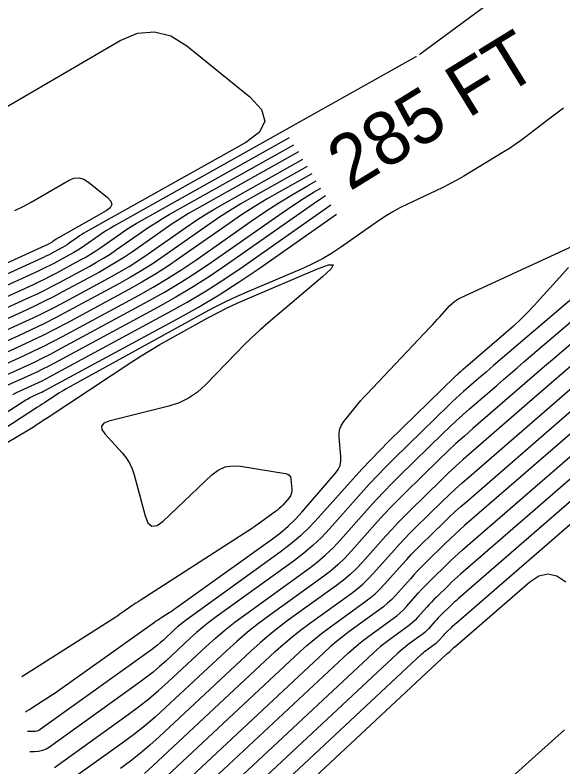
# Model space of a CAD drawing. Extents: x 1768942 to 1774819, y 723037 to 732099.
# Drawn here: x 1770484.7 to 1770546.4, y 726452.6 to 726537.2 of the extents above; entities that cross this region are included whole.
import ezdxf

# ---------------------------------------------------------------- set-up
doc = ezdxf.new("R2010")
doc.units = 0
doc.layers.add('R_Contour Annot', color=7, linetype='Continuous')
doc.layers.add('R_Contours', color=7, linetype='Continuous')

msp = doc.modelspace()

# ---------------------------------------------------------------- linework, layer by layer
at = {"layer": 'R_Contours'}
for points in [[(1770569.11, 726561.412), (1770530.313, 726532.796), (1770530.288, 726532.777), (1770530.263, 726532.757), (1770530.241, 726532.741)], [(1770478.44, 726523.752), (1770496.565, 726534.321), (1770498.514, 726535.148), (1770500.412, 726535.328), (1770502.261, 726534.86), (1770504.06, 726533.745), (1770511.158, 726527.991), (1770512.461, 726526.593), (1770512.823, 726525.275), (1770512.243, 726524.037), (1770510.721, 726522.88), (1770492.736, 726512.797), (1770492.488, 726512.653), (1770492.244, 726512.504), (1770492.003, 726512.348), (1770491.766, 726512.187), (1770490.827, 726511.529), (1770490.59, 726511.368), (1770490.348, 726511.214), (1770490.102, 726511.067), (1770489.852, 726510.927), (1770488.762, 726510.338), (1770488.495, 726510.197), (1770488.225, 726510.06), (1770487.954, 726509.928), (1770487.68, 726509.801), (1770464.867, 726499.407)], [(1770529.896, 726532.528), (1770529.881, 726532.522), (1770529.856, 726532.51), (1770529.831, 726532.497), (1770529.806, 726532.484), (1770495.854, 726513.448), (1770495.432, 726513.205), (1770495.016, 726512.951), (1770494.607, 726512.686), (1770494.205, 726512.412), (1770492.607, 726511.292), (1770492.204, 726511.019), (1770491.793, 726510.757), (1770491.375, 726510.507), (1770490.95, 726510.269), (1770489.095, 726509.268), (1770488.641, 726509.027), (1770488.183, 726508.795), (1770487.721, 726508.57), (1770487.256, 726508.353), (1770466.953, 726499.103)], [(1770546.443, 726526.741), (1770545.83, 726526.292), (1770545.222, 726525.837), (1770544.618, 726525.375), (1770542.213, 726523.517), (1770541.606, 726523.061), (1770540.986, 726522.624), (1770540.354, 726522.205), (1770539.709, 726521.804), (1770535.203, 726519.089), (1770534.433, 726518.639), (1770533.651, 726518.21), (1770532.859, 726517.801), (1770532.056, 726517.413), (1770528.821, 726515.901), (1770528.021, 726515.507), (1770527.241, 726515.079), (1770526.481, 726514.617), (1770525.74, 726514.123), (1770521.337, 726511.045), (1770520.344, 726510.389), (1770519.321, 726509.787), (1770518.269, 726509.24), (1770517.185, 726508.747), (1770511.082, 726506.158), (1770509.707, 726505.554), (1770508.35, 726504.915), (1770507.009, 726504.241), (1770505.685, 726503.533), (1770490.481, 726495.139), (1770490.204, 726494.982), (1770489.93, 726494.82), (1770489.659, 726494.652), (1770489.392, 726494.479), (1770488.329, 726493.777), (1770488.063, 726493.601), (1770487.797, 726493.427), (1770487.53, 726493.252), (1770487.263, 726493.079), (1770478.809, 726487.603)], [(1770469.039, 726498.799), (1770486.831, 726506.906), (1770487.489, 726507.212), (1770488.141, 726507.529), (1770488.787, 726507.858), (1770489.428, 726508.197), (1770492.047, 726509.611), (1770492.648, 726509.947), (1770493.238, 726510.3), (1770493.818, 726510.669), (1770494.387, 726511.056), (1770496.643, 726512.636), (1770497.212, 726513.024), (1770497.789, 726513.397), (1770498.376, 726513.756), (1770498.972, 726514.1), (1770515.606, 726523.426)], [(1770471.124, 726498.496), (1770486.407, 726505.458), (1770487.256, 726505.854), (1770488.098, 726506.264), (1770488.934, 726506.688), (1770489.762, 726507.126), (1770493.144, 726508.953), (1770493.92, 726509.387), (1770494.683, 726509.843), (1770495.432, 726510.32), (1770496.167, 726510.82), (1770499.081, 726512.861), (1770499.816, 726513.362), (1770500.562, 726513.844), (1770501.32, 726514.307), (1770502.09, 726514.752), (1770516.108, 726522.611)], [(1770516.61, 726521.796), (1770505.209, 726515.404), (1770504.265, 726514.859), (1770503.335, 726514.291), (1770502.42, 726513.7), (1770501.52, 726513.086), (1770497.947, 726510.583), (1770497.046, 726509.971), (1770496.128, 726509.386), (1770495.193, 726508.827), (1770494.242, 726508.295), (1770490.095, 726506.056), (1770489.08, 726505.518), (1770488.056, 726504.999), (1770487.023, 726504.496), (1770485.982, 726504.011), (1770473.21, 726498.192)], [(1770475.296, 726497.888), (1770485.558, 726502.564), (1770486.791, 726503.138), (1770488.014, 726503.733), (1770489.226, 726504.349), (1770490.429, 726504.985), (1770495.339, 726507.637), (1770496.466, 726508.267), (1770497.572, 726508.928), (1770498.66, 726509.622), (1770499.727, 726510.347), (1770503.958, 726513.31), (1770505.025, 726514.038), (1770506.108, 726514.737), (1770507.209, 726515.41), (1770508.327, 726516.055), (1770517.112, 726520.981)], [(1770517.614, 726520.166), (1770511.445, 726516.707), (1770510.153, 726515.961), (1770508.881, 726515.184), (1770507.629, 726514.375), (1770506.397, 726513.535), (1770501.507, 726510.11), (1770500.274, 726509.272), (1770499.017, 726508.471), (1770497.738, 726507.707), (1770496.437, 726506.979), (1770490.762, 726503.914), (1770489.372, 726503.179), (1770487.971, 726502.468), (1770486.558, 726501.78), (1770485.133, 726501.116), (1770477.382, 726497.584)], [(1770518.116, 726519.351), (1770514.563, 726517.359), (1770513.097, 726516.513), (1770511.654, 726515.631), (1770510.233, 726514.713), (1770508.835, 726513.76), (1770503.287, 726509.874), (1770501.888, 726508.923), (1770500.462, 726508.014), (1770499.011, 726507.147), (1770497.534, 726506.321), (1770490.564, 726502.557), (1770489.254, 726501.864), (1770487.933, 726501.193), (1770486.601, 726500.545), (1770485.258, 726499.919), (1770479.467, 726497.281)], [(1770484.725, 726515.23), (1770485.661, 726515.653), (1770486.571, 726516.143), (1770490.764, 726518.588), (1770491.348, 726518.836), (1770491.916, 726518.89), (1770492.469, 726518.75), (1770493.008, 726518.416), (1770495.133, 726516.693), (1770495.523, 726516.275), (1770495.631, 726515.88), (1770495.457, 726515.51), (1770495.002, 726515.163), (1770489.618, 726512.145), (1770489.544, 726512.102), (1770489.471, 726512.057), (1770489.399, 726512.011), (1770489.328, 726511.962), (1770489.046, 726511.765), (1770488.976, 726511.717), (1770488.903, 726511.671), (1770488.83, 726511.627), (1770488.755, 726511.585), (1770488.428, 726511.409), (1770488.348, 726511.367), (1770488.268, 726511.326), (1770488.187, 726511.286), (1770488.105, 726511.248), (1770462.781, 726499.71)], [(1770481.223, 726496.826), (1770485.685, 726498.86), (1770486.796, 726499.377), (1770487.898, 726499.913), (1770488.991, 726500.468), (1770490.074, 726501.042), (1770498.631, 726505.663), (1770500.284, 726506.587), (1770501.907, 726507.557), (1770503.502, 726508.574), (1770505.068, 726509.637), (1770511.296, 726514), (1770512.849, 726515.059), (1770514.426, 726516.078), (1770516.029, 726517.057), (1770517.656, 726517.997), (1770518.618, 726518.536)], [(1770482.584, 726496.193), (1770486.113, 726497.8), (1770486.991, 726498.21), (1770487.863, 726498.634), (1770488.727, 726499.073), (1770489.584, 726499.526), (1770499.729, 726505.005), (1770501.556, 726506.027), (1770503.352, 726507.1), (1770505.116, 726508.225), (1770506.848, 726509.401), (1770514.793, 726514.966), (1770515.978, 726515.774), (1770517.182, 726516.552), (1770518.405, 726517.3), (1770519.124, 726517.715)], [(1770519.659, 726516.846), (1770519.107, 726516.49), (1770518.289, 726515.932), (1770508.628, 726509.164), (1770506.73, 726507.875), (1770504.797, 726506.643), (1770502.829, 726505.467), (1770500.826, 726504.348), (1770489.093, 726498.01), (1770488.463, 726497.677), (1770487.827, 726497.354), (1770487.187, 726497.042), (1770486.54, 726496.741), (1770483.944, 726495.559)], [(1770484.49, 726494.517), (1770484.894, 726494.728), (1770485.305, 726494.925), (1770486.968, 726495.682), (1770487.382, 726495.875), (1770487.792, 726496.075), (1770488.199, 726496.281), (1770488.603, 726496.495), (1770501.924, 726503.69), (1770504.102, 726504.907), (1770506.242, 726506.186), (1770508.344, 726507.526), (1770510.408, 726508.928), (1770520.278, 726515.842)], [(1770476.003, 726487.512), (1770485.965, 726493.908), (1770486.135, 726494.013), (1770486.309, 726494.112), (1770486.486, 726494.205), (1770486.666, 726494.291), (1770487.395, 726494.623), (1770487.577, 726494.707), (1770487.757, 726494.795), (1770487.935, 726494.886), (1770488.112, 726494.979), (1770503.021, 726503.032), (1770505.374, 726504.347), (1770507.687, 726505.729), (1770509.958, 726507.177), (1770512.188, 726508.691), (1770520.916, 726514.805)], [(1770485.923, 726458.831), (1770486.034, 726458.899), (1770486.295, 726459.063), (1770488.027, 726460.163), (1770488.401, 726460.404), (1770488.772, 726460.65), (1770489.14, 726460.9), (1770489.504, 726461.155), (1770500.427, 726468.905), (1770500.63, 726469.047), (1770500.834, 726469.186), (1770501.04, 726469.323), (1770501.247, 726469.458), (1770502.081, 726469.993), (1770502.288, 726470.128), (1770502.494, 726470.265), (1770502.698, 726470.405), (1770502.9, 726470.548), (1770513.714, 726478.288), (1770514.615, 726478.974), (1770515.47, 726479.709), (1770516.28, 726480.494), (1770517.044, 726481.328), (1770520.803, 726485.681), (1770521.1, 726486.098), (1770521.298, 726486.546), (1770521.398, 726487.027), (1770521.399, 726487.538), (1770521.202, 726489.704), (1770521.201, 726490.191), (1770521.29, 726490.65), (1770521.469, 726491.083), (1770521.737, 726491.489), (1770522.989, 726493.058), (1770523.306, 726493.447), (1770523.631, 726493.829), (1770523.964, 726494.204), (1770524.305, 726494.572), (1770531.399, 726502.066), (1770531.68, 726502.365), (1770531.959, 726502.665), (1770532.237, 726502.967), (1770532.514, 726503.27), (1770533.616, 726504.485), (1770533.904, 726504.772), (1770534.216, 726505.027), (1770534.552, 726505.248), (1770534.912, 726505.436), (1770550.369, 726512.559)], [(1770474.411, 726483.519), (1770486.249, 726490.55), (1770486.438, 726490.664), (1770486.626, 726490.779), (1770486.813, 726490.896), (1770486.998, 726491.015), (1770487.739, 726491.495), (1770487.924, 726491.615), (1770488.108, 726491.736), (1770488.293, 726491.857), (1770488.477, 726491.978), (1770497.882, 726498.196), (1770498.918, 726498.866), (1770499.967, 726499.515), (1770501.028, 726500.143), (1770502.103, 726500.75), (1770506.425, 726503.137), (1770507.513, 726503.719), (1770508.615, 726504.273), (1770509.73, 726504.798), (1770510.86, 726505.294), (1770518.766, 726508.648), (1770520.007, 726509.104), (1770520.513, 726509.106), (1770520.283, 726508.656), (1770519.318, 726507.752), (1770513.214, 726502.577), (1770512.279, 726501.763), (1770511.364, 726500.925), (1770510.472, 726500.065), (1770509.601, 726499.182), (1770506.162, 726495.603), (1770505.259, 726494.782), (1770504.27, 726494.109), (1770503.196, 726493.584), (1770502.035, 726493.206), (1770495.287, 726491.505), (1770494.735, 726491.283), (1770494.48, 726490.973), (1770494.521, 726490.573), (1770494.86, 726490.084), (1770496.807, 726487.949), (1770497.256, 726487.395), (1770497.63, 726486.799), (1770497.928, 726486.163), (1770498.15, 726485.485), (1770499.371, 726480.866), (1770499.697, 726480.078), (1770500.145, 726479.719), (1770500.715, 726479.788), (1770501.407, 726480.287), (1770506.881, 726485.468), (1770507.599, 726486.018), (1770508.378, 726486.367), (1770509.218, 726486.515), (1770510.12, 726486.463), (1770515.164, 726485.64), (1770515.409, 726485.566), (1770515.591, 726485.433), (1770515.711, 726485.242), (1770515.768, 726484.992), (1770515.871, 726483.861), (1770515.87, 726483.598), (1770515.819, 726483.35), (1770515.716, 726483.119), (1770515.563, 726482.904), (1770514.849, 726482.076), (1770514.665, 726481.876), (1770514.47, 726481.687), (1770514.264, 726481.51), (1770514.047, 726481.345), (1770512.134, 726479.975), (1770511.739, 726479.696), (1770511.341, 726479.423), (1770510.939, 726479.154), (1770510.534, 726478.89), (1770498.81, 726471.369), (1770498.578, 726471.218), (1770498.348, 726471.065), (1770498.12, 726470.909), (1770497.893, 726470.75), (1770496.991, 726470.11), (1770496.765, 726469.952), (1770496.537, 726469.796), (1770496.306, 726469.644), (1770496.074, 726469.494), (1770485.492, 726462.773)], [(1770547.007, 726508.804), (1770543.129, 726504.529), (1770542.382, 726503.73), (1770541.61, 726502.956), (1770540.814, 726502.207), (1770539.994, 726501.483), (1770535.158, 726497.345), (1770535.08, 726497.278), (1770535.002, 726497.211), (1770534.924, 726497.144), (1770534.846, 726497.077), (1770534.536, 726496.808), (1770534.459, 726496.74), (1770534.383, 726496.671), (1770534.308, 726496.601), (1770534.234, 726496.529), (1770526.801, 726489.266), (1770525.766, 726488.236), (1770524.749, 726487.189), (1770523.75, 726486.125), (1770522.77, 726485.043), (1770518.885, 726480.68), (1770517.887, 726479.619), (1770516.835, 726478.617), (1770515.731, 726477.674), (1770514.573, 726476.79), (1770504.033, 726469.188), (1770503.686, 726468.929), (1770503.347, 726468.659), (1770503.016, 726468.379), (1770502.695, 726468.088), (1770501.426, 726466.903), (1770501.105, 726466.612), (1770500.774, 726466.332), (1770500.435, 726466.063), (1770500.086, 726465.805), (1770487.584, 726456.847), (1770487.413, 726456.743), (1770487.232, 726456.669), (1770487.041, 726456.625), (1770486.841, 726456.612), (1770486.165, 726456.617)], [(1770550.656, 726508.106), (1770538.573, 726497.767), (1770538.15, 726497.405), (1770537.727, 726497.041), (1770537.305, 726496.677), (1770536.884, 726496.312), (1770535.199, 726494.852), (1770534.781, 726494.484), (1770534.368, 726494.11), (1770533.961, 726493.73), (1770533.56, 726493.343), (1770527.394, 726487.317), (1770526.443, 726486.371), (1770525.508, 726485.409), (1770524.591, 726484.431), (1770523.69, 726483.437), (1770520.121, 726479.43), (1770519.204, 726478.455), (1770518.238, 726477.534), (1770517.223, 726476.668), (1770516.16, 726475.856), (1770507.359, 726469.508), (1770506.604, 726468.945), (1770505.868, 726468.359), (1770505.15, 726467.75), (1770504.452, 726467.118), (1770501.696, 726464.544), (1770500.997, 726463.912), (1770500.279, 726463.304), (1770499.542, 726462.72), (1770498.785, 726462.159), (1770488.615, 726454.872), (1770488.231, 726454.639), (1770487.826, 726454.473), (1770487.399, 726454.375), (1770486.951, 726454.345), (1770486.413, 726454.349)], [(1770489.168, 726452.554), (1770497.484, 726458.513), (1770498.649, 726459.377), (1770499.784, 726460.277), (1770500.89, 726461.213), (1770501.966, 726462.185), (1770506.209, 726466.148), (1770507.284, 726467.121), (1770508.389, 726468.059), (1770509.522, 726468.961), (1770510.685, 726469.828), (1770517.746, 726474.921), (1770518.716, 726475.662), (1770519.641, 726476.451), (1770520.521, 726477.29), (1770521.357, 726478.179), (1770524.61, 726481.832), (1770525.431, 726482.738), (1770526.267, 726483.629), (1770527.119, 726484.506), (1770527.986, 726485.368), (1770532.886, 726490.157), (1770533.614, 726490.858), (1770534.353, 726491.549), (1770535.103, 726492.228), (1770535.862, 726492.897), (1770538.921, 726495.548), (1770539.686, 726496.21), (1770540.453, 726496.871), (1770541.22, 726497.531), (1770541.988, 726498.19), (1770552.137, 726506.873)], [(1770553.617, 726505.64), (1770545.404, 726498.612), (1770544.29, 726497.657), (1770543.178, 726496.701), (1770542.068, 726495.743), (1770540.959, 726494.784), (1770536.24, 726490.694), (1770535.281, 726489.85), (1770534.335, 726488.992), (1770533.402, 726488.12), (1770532.482, 726487.234), (1770528.578, 726483.419), (1770527.796, 726482.641), (1770527.027, 726481.849), (1770526.272, 726481.045), (1770525.53, 726480.227), (1770522.593, 726476.928), (1770521.838, 726476.126), (1770521.043, 726475.368), (1770520.208, 726474.655), (1770519.333, 726473.987), (1770513.404, 726469.711), (1770512.134, 726468.763), (1770510.895, 726467.777), (1770509.688, 726466.753), (1770508.512, 726465.689), (1770501.677, 726459.306), (1770500.508, 726458.248), (1770499.305, 726457.23), (1770498.071, 726456.251), (1770496.804, 726455.312), (1770489.72, 726450.236)], [(1770547.271, 726497.708), (1770545.903, 726496.532), (1770544.537, 726495.353), (1770543.173, 726494.173), (1770536.009, 726487.963), (1770535.153, 726487.21), (1770534.308, 726486.444), (1770533.476, 726485.666), (1770532.654, 726484.875), (1770529.171, 726481.471), (1770528.472, 726480.776), (1770527.786, 726480.07), (1770527.112, 726479.351), (1770526.45, 726478.621), (1770523.829, 726475.677), (1770523.155, 726474.961), (1770522.446, 726474.285), (1770521.7, 726473.649), (1770520.919, 726473.052), (1770515.628, 726469.236), (1770514.494, 726468.391), (1770513.389, 726467.511), (1770512.311, 726466.596), (1770511.262, 726465.647), (1770500.958, 726456.023), (1770499.913, 726455.078), (1770498.838, 726454.168), (1770497.735, 726453.294), (1770496.603, 726452.454)], [(1770495.923, 726433.047), (1770530.512, 726465.351), (1770530.676, 726465.5), (1770530.845, 726465.643), (1770531.018, 726465.781), (1770531.196, 726465.913), (1770532.025, 726466.511), (1770532.147, 726466.605), (1770532.264, 726466.704), (1770532.375, 726466.81), (1770532.481, 726466.922), (1770532.891, 726467.383), (1770532.995, 726467.498), (1770533.1, 726467.61), (1770533.208, 726467.721), (1770533.317, 726467.83), (1770533.863, 726468.363), (1770533.992, 726468.487), (1770534.122, 726468.609), (1770534.254, 726468.729), (1770534.388, 726468.847), (1770564.825, 726495.228)], [(1770561.732, 726495.077), (1770534.62, 726471.578), (1770534.383, 726471.369), (1770534.149, 726471.157), (1770533.918, 726470.941), (1770533.69, 726470.722), (1770532.725, 726469.778), (1770532.531, 726469.586), (1770532.341, 726469.39), (1770532.154, 726469.191), (1770531.971, 726468.989), (1770531.245, 726468.173), (1770531.058, 726467.975), (1770530.861, 726467.787), (1770530.655, 726467.611), (1770530.438, 726467.446), (1770528.972, 726466.388), (1770528.658, 726466.154), (1770528.351, 726465.91), (1770528.053, 726465.656), (1770527.762, 726465.393), (1770496.642, 726436.329)], [(1770558.639, 726494.927), (1770534.851, 726474.309), (1770534.511, 726474.009), (1770534.175, 726473.705), (1770533.844, 726473.395), (1770533.518, 726473.081), (1770532.133, 726471.727), (1770531.855, 726471.451), (1770531.582, 726471.17), (1770531.314, 726470.884), (1770531.051, 726470.594), (1770530.009, 726469.424), (1770529.741, 726469.139), (1770529.459, 726468.87), (1770529.162, 726468.617), (1770528.852, 726468.38), (1770526.748, 726466.863), (1770526.297, 726466.526), (1770525.858, 726466.177), (1770525.429, 726465.813), (1770525.012, 726465.436), (1770497.362, 726439.611)], [(1770498.081, 726442.894), (1770522.262, 726465.478), (1770522.806, 726465.97), (1770523.364, 726466.443), (1770523.937, 726466.899), (1770524.524, 726467.337), (1770527.265, 726469.315), (1770527.67, 726469.624), (1770528.056, 726469.953), (1770528.424, 726470.304), (1770528.773, 726470.674), (1770530.131, 726472.2), (1770530.474, 726472.578), (1770530.823, 726472.95), (1770531.178, 726473.316), (1770531.54, 726473.676), (1770533.345, 726475.44), (1770533.77, 726475.849), (1770534.202, 726476.253), (1770534.639, 726476.649), (1770535.083, 726477.039), (1770555.546, 726494.776)], [(1770499.318, 726451.908), (1770500.239, 726452.741), (1770514.012, 726465.605), (1770514.935, 726466.439), (1770515.882, 726467.244), (1770516.855, 726468.018), (1770517.852, 726468.761), (1770522.506, 726472.118), (1770523.193, 726472.643), (1770523.848, 726473.202), (1770524.472, 726473.797), (1770525.065, 726474.427), (1770527.37, 726477.016), (1770527.952, 726477.658), (1770528.545, 726478.29), (1770529.149, 726478.911), (1770529.763, 726479.522), (1770532.827, 726482.516), (1770533.549, 726483.212), (1770534.282, 726483.896), (1770535.024, 726484.57), (1770535.777, 726485.232), (1770546.266, 726494.324), (1770547.446, 726495.345)], [(1770552.453, 726494.625), (1770535.314, 726479.77), (1770534.768, 726479.289), (1770534.229, 726478.8), (1770533.697, 726478.304), (1770533.172, 726477.799), (1770530.948, 726475.625), (1770530.502, 726475.181), (1770530.064, 726474.73), (1770529.633, 726474.271), (1770529.211, 726473.805), (1770527.537, 726471.925), (1770527.107, 726471.468), (1770526.654, 726471.036), (1770526.178, 726470.63), (1770525.679, 726470.249), (1770522.3, 726467.812), (1770521.576, 726467.272), (1770520.87, 726466.71), (1770520.182, 726466.126), (1770519.512, 726465.52), (1770498.8, 726446.176)], [(1770499.52, 726449.459), (1770516.762, 726465.562), (1770517.558, 726466.283), (1770518.376, 726466.977), (1770519.215, 726467.645), (1770520.076, 726468.287), (1770524.092, 726471.183), (1770524.685, 726471.636), (1770525.251, 726472.119), (1770525.789, 726472.632), (1770526.301, 726473.176), (1770528.291, 726475.41), (1770528.793, 726475.965), (1770529.304, 726476.51), (1770529.825, 726477.046), (1770530.356, 726477.573), (1770533, 726480.157), (1770533.623, 726480.758), (1770534.255, 726481.348), (1770534.896, 726481.93), (1770535.546, 726482.501), (1770549.36, 726494.475)], [(1770495.204, 726429.764), (1770533.262, 726465.309), (1770533.3, 726465.343), (1770533.339, 726465.376), (1770533.379, 726465.408), (1770533.42, 726465.439), (1770533.611, 726465.577), (1770533.64, 726465.598), (1770533.667, 726465.621), (1770533.692, 726465.646), (1770533.717, 726465.672), (1770533.811, 726465.778), (1770533.835, 726465.804), (1770533.86, 726465.83), (1770533.884, 726465.856), (1770533.91, 726465.881), (1770534.036, 726466.004), (1770534.065, 726466.033), (1770534.096, 726466.061), (1770534.126, 726466.089), (1770534.157, 726466.116), (1770542.631, 726473.461), (1770543.651, 726474.124), (1770544.67, 726474.345), (1770545.69, 726474.124), (1770546.71, 726473.462)], [(1770546.534, 726456.821), (1770526.779, 726439.076)]]:
    msp.add_lwpolyline(points, dxfattribs=at)

# ---------------------------------------------------------------- texts
at = {"layer": 'R_Contour Annot'}
msp.add_text('285 FT', height=6, rotation=31.6373, dxfattribs=at).set_placement((1770522.385, 726517.33))

doc.saveas('drawing.dxf')
